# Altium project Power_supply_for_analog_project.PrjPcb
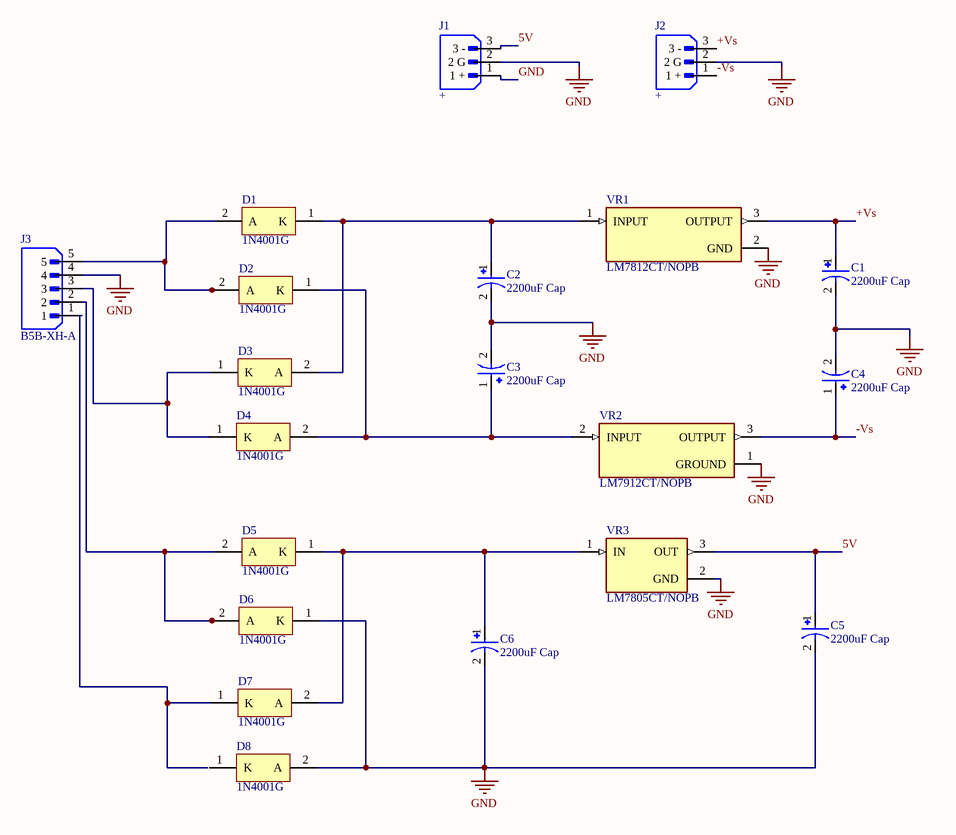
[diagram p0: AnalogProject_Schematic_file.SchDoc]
1 sheet, 20 parts. Net scope: global (net labels, ports and power ports of the same name join across sheets).
Board file: AnalogProject_PCBDoc.PcbDoc

## Sheet AnalogProject_Schematic_file.SchDoc
size A4; SheetNumber: 1; SheetTotal: 1

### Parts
C1  2200uF Cap  [2200uF Cap]
C2  2200uF Cap  [2200uF Cap]
C3  2200uF Cap  [2200uF Cap]
C4  2200uF Cap  [2200uF Cap]
C5  2200uF Cap  [2200uF Cap]
C6  2200uF Cap  [2200uF Cap]
D1  1N4001G  [1N4001_diode]
D2  1N4001G  [1N4001_diode]
D3  1N4001G  [1N4001_diode]
D4  1N4001G  [1N4001_diode]
D5  1N4001G  [1N4001_diode]
D6  1N4001G  [1N4001_diode]
D7  1N4001G  [1N4001_diode]
D8  1N4001G  [1N4001_diode]
J1  +  [JST_B3B-XH-A]
J2  +  [JST_B3B-XH-A]
J3  B5B-XH-A  [JST_B5B-XH-A]
VR1  LM7812CT/NOPB  [LM7812]
VR2  LM7912CT/NOPB  [LM7912]
VR3  LM7805CT/NOPB  [LM7805]

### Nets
GND: C1.2(N) C2.2(N) C3.2(N) C4.2(N) C5.2(N) C6.2(N) D6.1(K) D8.2(A) J1.1(1_+) J1.2(2_G) J2.2(2_G) J3.4 VR1.2(GND) VR2.1(GROUND) VR3.2(GND)
5V: C5.1(P) J1.3(3_-) VR3.3(OUT)
+Vs: C1.1(P) J2.3(3_-) VR1.3(OUTPUT)
-Vs: C4.1(P) J2.1(1_+) VR2.3(OUTPUT)
NetC2_1: C2.1(P) D1.1(K) D3.2(A) VR1.1(INPUT)
NetC3_1: C3.1(P) D2.1(K) D4.2(A) VR2.2(INPUT)
NetC6_1: C6.1(P) D5.1(K) D7.2(A) VR3.1(IN)
NetD1_2: D1.2(A) D2.2(A) J3.5
NetD3_1: D3.1(K) D4.1(K) J3.3
NetD5_2: D5.2(A) D6.2(A) J3.2
NetD7_1: D7.1(K) J3.1

Not connected (* = marked no-connect by the designer): D8 1(K)

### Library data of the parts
C1-C6 = 2200uF Cap: 2200 ÂµF 25 V Aluminum Electrolytic Capacitors Radial, Can - 5000 Hrs @ 105Â°C; MP: EEUFC1E222; MF: Panasonic
D1-D8 = CMP-0902-00120-1: Diode, Rectifier, Standard, Vr 50V, If 1A, Pkg SOD57, Vf 0.93V, Tj +175C, Cs 30A, Ir 1UA; Manufacturer: On Semiconductor; Manufacturer Lifecycle Status: ACTIVE; Packing: Bulk Bag; IFSM Max (A): 30; Type: Standard Recovery; VRRM Max (V): 50; IO(rec) Max (A): 1; Element Configuration: Single; Forward Voltage: 1.1V; Peak Reverse Current: 10µA
J1 J2 = B3B-XH-A: Connector Header Through Hole 3 position 0.098 (2.50mm); MF: JST Sales
J3 = B5B-XH-A: Connector Header Through Hole 5 position 0.098 (2.50mm); MF: JST Sales
VR1 = LM7812CT/NOPB: 1.5-A, 30-V, linear voltage regulator; MF: Texas Instruments
VR2 = LM7912CT/NOPB: 1.5-A, negative linear voltage regulator; MF: Texas Instruments
VR3 = LM7805CT/NOPB: Linear Voltage Regulator IC Positive Fixed 1 Output 1.5A TO-220-3; MF: ON Semiconductor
